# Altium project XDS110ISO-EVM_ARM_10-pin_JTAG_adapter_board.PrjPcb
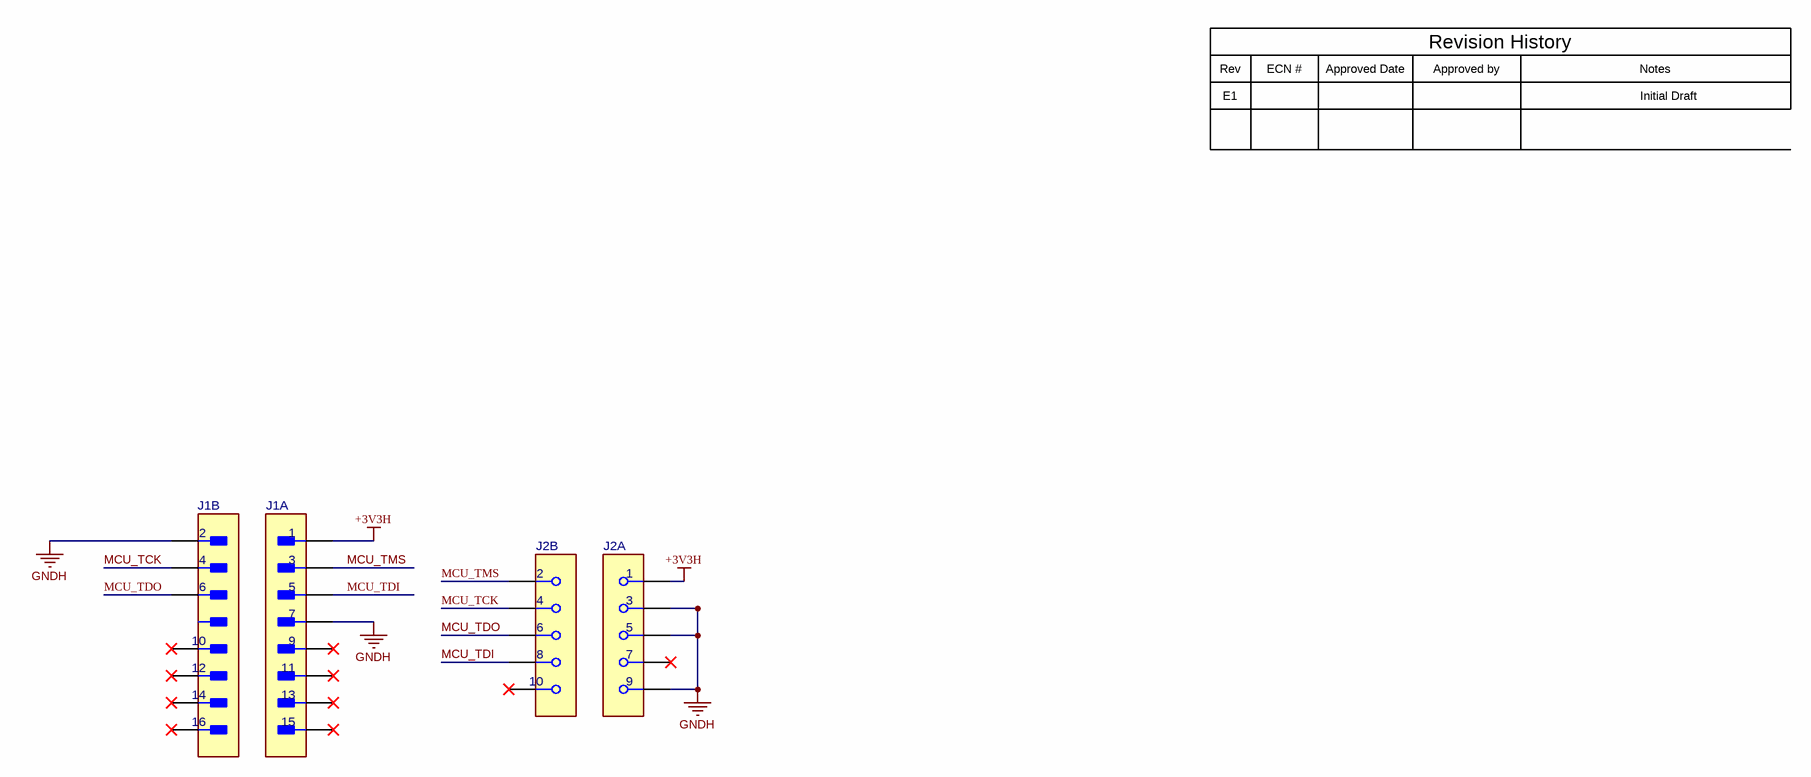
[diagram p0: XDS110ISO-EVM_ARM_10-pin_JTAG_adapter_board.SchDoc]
TID: N/A; TechSupport: http://www.ti.com/support; SCH_Rev: A; PRJ_Number: XDS110ISO-EVM_ARM_10-pin_JTAG_adapter_board; PRJ_Engineer: Sumit Patil; PRJ_Customer: XDS110ISO-EVM; PCB_Rev: E1; PCB_Layout: Sumit Patil; Orderable: XDS110ISO-EVM_ARM_10-pin_JTAG_adapter_board; DrawnBy: Sumit Patil; CopyrightYear: 2022
1 sheet, 2 parts. Net scope: global (net labels, ports and power ports of the same name join across sheets).
Board file: XDS110ISO-EVM_ARM_10-pin_JTAG_adapter_board.PcbDoc

## Sheet XDS110ISO-EVM_ARM_10-pin_JTAG_adapter_board.SchDoc
size 431 x 279 mm; Date: Not shown in title block; ApprovedBy: Not shown in title block; CheckedBy: Not shown in title block; Author: Not shown in title block; CompanyName: Not shown in title block; DrawnBy: Cody Watkins; Engineer: Not shown in title block; Organization: Not shown in title block; Address1: Not shown in title block; Address2: Not shown in title block; Address3: Not shown in title block; Address4: Not shown in title block; DocumentNumber: 1; Revision: Use project parameter SCH_Rev; SheetNumber: 1; SheetTotal: 8; PageSetup: Record=PageOptions¦CenterHorizontal=True¦CenterVertical=True¦PrintScale=1.00¦XCorrection=1.00¦YCorrection=1.00¦PrintKind=0¦BorderSize=5000000¦LeftOffset=0¦BottomOffset=0¦Orientation=2¦PaperLength=1000¦PaperWidth=1000¦Scale=100¦PaperSource=15¦PrintQuality=600¦MediaType=1¦DitherType=10¦PaperKind=Letter¦PrintScaleMode=1

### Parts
J1  TSM-108-01-L-DV-008-P-TR  [FP-TSM-108-01-L-DV-008-P-TR_HDR15-MFG]  (value not drawn)  (parts A,B of 2)
J2  SFMC-105-02-S-D-K-TR  [FP-SFMC-105-02-S-D-K-TR_CONN_RCPT10-MFG]  (value not drawn)  (parts A,B of 2)

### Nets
+3V3H: J1.1 J2.1
GNDH: J1.2 J1.7 J2.3 J2.5 J2.9
MCU_TCK: J1.4 J2.4
MCU_TDI: J1.5 J2.8
MCU_TDO: J1.6 J2.6
MCU_TMS: J1.3 J2.2

Not connected (* = marked no-connect by the designer): J1 9* 10* 11* 12* 13* 14* 15* 16*; J2 7* 10*

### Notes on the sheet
- Rev
- E1
- ECN #
- Approved Date
- Approved by
- Revision History
- Notes
- Initial Draft

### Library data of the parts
J1 = CMP-0121706-1: Conn Unshrouded HDR 16 POS 2.54mm Solder ST SMT; Manufacturer: Samtec; ContactFinish: Gold,Nickel; Row_Count: 2; AEC Qualified: No; Conn Gender: Male; Conn Orientation: Vertical; SizeZ_mm: 10.16mm; Standoff Height: 1.02mm
J2 = CMP-0121829-1: 10 Position Receptacle Connector 0.050" (1.27mm) Surface Mount Gold; Manufacturer: Samtec; ContactFinish: Gold,Nickel; Current_A: 2.9A; Row_Count: 2; Voltage_V: 310V; AEC Qualified: No; Conn Gender: Female; Conn Orientation: Vertical; Is Female: yes; SizeZ_mm: 4.751mm

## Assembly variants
001: not fitted FID1 FID2 FID3 FID4 FID5 FID6 R17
